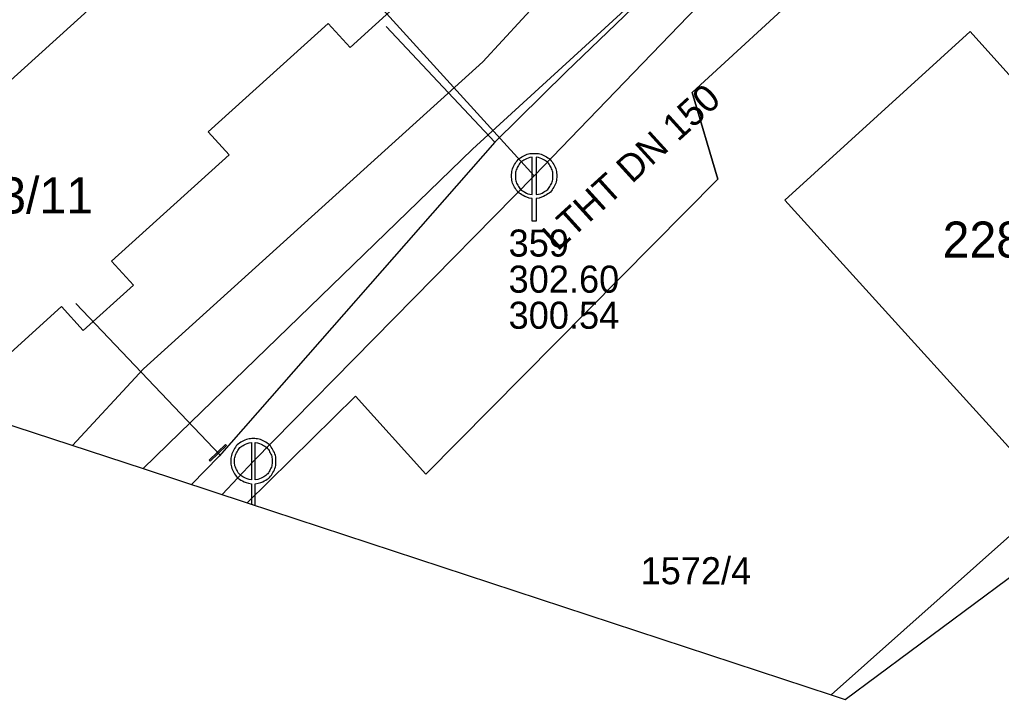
# Model space of a CAD drawing. Extents: x -570890 to -570546, y -1086481 to -1086296.
# Drawn here: x -570739.5 to -570685, y -1086481.2 to -1086443.5 of the extents above; entities that cross this region are included whole.
import ezdxf

# ---------------------------------------------------------------- set-up
doc = ezdxf.new("R2010")
doc.units = 0
for name, color, linetype in [('Adresní místo-text', 7, 'Continuous'), ('Armatura vodovodní', 7, 'Continuous'), ('Default', 7, 'Continuous'), ('Kanalizační přípojka', 7, 'Continuous'), ('Kanalizační stoka', 7, 'Continuous'), ('Kanalizační šachta', 7, 'Continuous'), ('Parcela-polygon', 7, 'Continuous'), ('Parcela-text', 7, 'Continuous'), ('Popis šachty', 7, 'Continuous'), ('Vodovodní přípojka', 7, 'Continuous'), ('Vodovodní řad', 7, 'Continuous'), ('Řad vodovodní popis', 7, 'Continuous')]:
    doc.layers.add(name, color=color, linetype=linetype)

msp = doc.modelspace()

# ---------------------------------------------------------------- linework, layer by layer
at = {"layer": 'Armatura vodovodní'}
msp.add_lwpolyline([(-570727.998, -1086467.114), (-570728.903, -1086467.976), (-570728.957, -1086467.919), (-570728.052, -1086467.058), (-570727.998, -1086467.114)], dxfattribs=at)
at = {"layer": 'Default'}
for points in [[(-570711.043, -1086453.418), (-570711.301, -1086453.4), (-570711.563, -1086453.254), (-570711.86, -1086453.09), (-570712.025, -1086452.793), (-570712.19, -1086452.495), (-570712.19, -1086452.17), (-570712.19, -1086451.843), (-570712.022, -1086451.543), (-570711.853, -1086451.242), (-570711.555, -1086451.081), (-570711.257, -1086450.92), (-570710.94, -1086450.92), (-570710.625, -1086450.92), (-570710.326, -1086451.081), (-570710.027, -1086451.242), (-570709.858, -1086451.543), (-570709.69, -1086451.843), (-570709.69, -1086452.17), (-570709.69, -1086452.495), (-570709.855, -1086452.793), (-570710.02, -1086453.09), (-570710.317, -1086453.254), (-570710.579, -1086453.4), (-570710.837, -1086453.418)], [(-570711.043, -1086451.132), (-570711.24, -1086451.149), (-570711.455, -1086451.264), (-570711.704, -1086451.399), (-570711.843, -1086451.649), (-570711.982, -1086451.899), (-570711.982, -1086452.17), (-570711.982, -1086452.441), (-570711.846, -1086452.688), (-570711.709, -1086452.934), (-570711.46, -1086453.071), (-570711.248, -1086453.191), (-570711.043, -1086453.205)], [(-570710.837, -1086453.205), (-570710.632, -1086453.191), (-570710.418, -1086453.071), (-570710.171, -1086452.934), (-570710.034, -1086452.688), (-570709.898, -1086452.441), (-570709.898, -1086452.17), (-570709.898, -1086451.899), (-570710.038, -1086451.649), (-570710.178, -1086451.399), (-570710.427, -1086451.264), (-570710.64, -1086451.149), (-570710.837, -1086451.132)]]:
    msp.add_open_spline(points, degree=3, dxfattribs=at)
at = {"layer": 'Kanalizační přípojka'}
msp.add_lwpolyline([(-570720.987, -1086441.102), (-570710.94, -1086452.17)], dxfattribs=at)
at = {"layer": 'Kanalizační stoka'}
for p, q in [((-570696.56, -1086437.24), (-570710.94, -1086452.17)), ((-570710.94, -1086452.17), (-570726.51, -1086467.98)), ((-570726.51, -1086467.98), (-570728.246, -1086469.83))]:
    msp.add_line(p, q, dxfattribs=at)
at = {"layer": 'Kanalizační šachta'}
for p, q in [((-570726.613, -1086466.942), (-570726.613, -1086469.015)), ((-570726.407, -1086469.015), (-570726.407, -1086466.942)), ((-570726.613, -1086469.228), (-570726.613, -1086470.366)), ((-570726.407, -1086470.434), (-570726.407, -1086469.228)), ((-570726.613, -1086470.366), (-570726.407, -1086470.434))]:
    msp.add_line(p, q, dxfattribs=at)
for points in [[(-570711.043, -1086453.205), (-570711.043, -1086451.132)], [(-570710.837, -1086451.132), (-570710.837, -1086453.205)], [(-570710.837, -1086453.418), (-570710.837, -1086454.67), (-570711.043, -1086454.67), (-570711.043, -1086453.418)]]:
    msp.add_lwpolyline(points, dxfattribs=at)
for points in [[(-570726.407, -1086469.228), (-570726.149, -1086469.21), (-570725.887, -1086469.064), (-570725.59, -1086468.9), (-570725.425, -1086468.603), (-570725.26, -1086468.305), (-570725.26, -1086467.98), (-570725.26, -1086467.653), (-570725.428, -1086467.353), (-570725.597, -1086467.052), (-570725.896, -1086466.891), (-570726.195, -1086466.73), (-570726.51, -1086466.73), (-570726.827, -1086466.73), (-570727.125, -1086466.891), (-570727.423, -1086467.052), (-570727.592, -1086467.353), (-570727.76, -1086467.653), (-570727.76, -1086467.98), (-570727.76, -1086468.305), (-570727.595, -1086468.603), (-570727.43, -1086468.9), (-570727.133, -1086469.064), (-570726.871, -1086469.21), (-570726.613, -1086469.228)], [(-570726.613, -1086469.015), (-570726.818, -1086469.001), (-570727.03, -1086468.881), (-570727.279, -1086468.744), (-570727.416, -1086468.498), (-570727.552, -1086468.251), (-570727.552, -1086467.98), (-570727.552, -1086467.709), (-570727.413, -1086467.459), (-570727.274, -1086467.209), (-570727.025, -1086467.074), (-570726.81, -1086466.959), (-570726.613, -1086466.942)], [(-570726.407, -1086466.942), (-570726.21, -1086466.959), (-570725.997, -1086467.074), (-570725.748, -1086467.209), (-570725.608, -1086467.459), (-570725.468, -1086467.709), (-570725.468, -1086467.98), (-570725.468, -1086468.251), (-570725.604, -1086468.498), (-570725.741, -1086468.744), (-570725.988, -1086468.881), (-570726.202, -1086469.001), (-570726.407, -1086469.015)]]:
    msp.add_open_spline(points, degree=3, dxfattribs=at)
at = {"layer": 'Parcela-polygon'}
for p, q in [((-570743.23, -1086464.907), (-570732.62, -1086468.393)), ((-570732.62, -1086468.393), (-570726.856, -1086470.287)), ((-570726.856, -1086470.287), (-570694.475, -1086480.924))]:
    msp.add_line(p, q, dxfattribs=at)
for points in [[(-570743.23, -1086464.907), (-570737.15, -1086459.41), (-570735.94, -1086460.74), (-570733.16, -1086458.23), (-570734.37, -1086456.9), (-570727.85, -1086451.01), (-570729.02, -1086449.73), (-570722.36, -1086443.72), (-570721.15, -1086445.06), (-570718.33, -1086442.51), (-570719.54, -1086441.17), (-570706.72, -1086429.59), (-570705.51, -1086430.93), (-570702.69, -1086428.39), (-570703.9, -1086427.05), (-570697.39, -1086421.17), (-570704.98, -1086412.95), (-570736.47, -1086441.32), (-570735.28, -1086442.64), (-570755.467, -1086460.887)], [(-570755.467, -1086460.887), (-570735.28, -1086442.64), (-570736.47, -1086441.32), (-570704.98, -1086412.95), (-570697.39, -1086421.17), (-570703.9, -1086427.05), (-570702.69, -1086428.39), (-570705.51, -1086430.93), (-570706.72, -1086429.59), (-570719.54, -1086441.17), (-570718.33, -1086442.51), (-570721.15, -1086445.06), (-570722.36, -1086443.72), (-570729.02, -1086449.73), (-570727.85, -1086451.01), (-570734.37, -1086456.9), (-570733.16, -1086458.23), (-570735.94, -1086460.74), (-570737.15, -1086459.41), (-570743.23, -1086464.907)], [(-570726.856, -1086470.287), (-570720.84, -1086464.38), (-570716.94, -1086468.7), (-570700.75, -1086452.36), (-570702.17, -1086447.55), (-570695.62, -1086441.51), (-570687.38, -1086434.77), (-570685.19, -1086433.4), (-570683.47, -1086432.73), (-570681.75, -1086432.33), (-570680.36, -1086432.34), (-570685.68, -1086426.55), (-570687.54, -1086424.56), (-570687.78, -1086425.47), (-570688.21, -1086426.47), (-570688.87, -1086427.37), (-570714.36, -1086450.68), (-570730.58, -1086466.4), (-570732.62, -1086468.393)], [(-570732.62, -1086468.393), (-570730.58, -1086466.4), (-570714.36, -1086450.68), (-570688.87, -1086427.37)], [(-570665.603, -1086460.368), (-570659.48, -1086455.08), (-570680.36, -1086432.34), (-570681.75, -1086432.33), (-570683.47, -1086432.73), (-570685.19, -1086433.4), (-570687.38, -1086434.77), (-570695.62, -1086441.51), (-570702.17, -1086447.55), (-570700.75, -1086452.36), (-570716.94, -1086468.7), (-570720.84, -1086464.38), (-570726.856, -1086470.287)], [(-570680.682, -1086471.538), (-570697.04, -1086453.52), (-570686.77, -1086444.17), (-570669.556, -1086463.296)], [(-570669.556, -1086463.296), (-570686.77, -1086444.17), (-570697.04, -1086453.52), (-570680.682, -1086471.538)], [(-570694.475, -1086480.924), (-570682.38, -1086470.18), (-570681.14, -1086471.877)], [(-570681.14, -1086471.877), (-570682.38, -1086470.18), (-570694.475, -1086480.924)], [(-570694.475, -1086480.924), (-570693.697, -1086481.179), (-570681.14, -1086471.877)]]:
    msp.add_lwpolyline(points, dxfattribs=at)
at = {"layer": 'Vodovodní přípojka'}
for points in [[(-570719.142, -1086443.892), (-570713.124, -1086450.31)], [(-570736.351, -1086459.244), (-570728.357, -1086467.643)]]:
    msp.add_lwpolyline(points, dxfattribs=at)
at = {"layer": 'Vodovodní řad'}
for points in [[(-570671.61, -1086415.74), (-570690.154, -1086424.461), (-570693.008, -1086425.972), (-570699.396, -1086431.613), (-570708.97, -1086440.64), (-570710.52, -1086442.29), (-570713.79, -1086445.84), (-570732.603, -1086462.857), (-570736.531, -1086467.108)], [(-570709.167, -1086446.396), (-570698.124, -1086435.809), (-570694.807, -1086432.821), (-570694.63, -1086433.04)], [(-570709.167, -1086446.396), (-570713.123, -1086450.309), (-570728.403, -1086467.695), (-570729.94, -1086469.273)]]:
    msp.add_lwpolyline(points, dxfattribs=at)

# ---------------------------------------------------------------- texts
at = {"layer": 'Adresní místo-text'}
for s, p in [('313/11', (-570743.581, -1086454.25)), ('228/12', (-570688.291, -1086456.7))]:
    msp.add_text(s, height=2, dxfattribs=at).set_placement(p)
at = {"layer": 'Parcela-text'}
msp.add_text('1572/4', height=1.5, dxfattribs=at).set_placement((-570705.04, -1086474.8))
at = {"layer": 'Popis šachty'}
for s, p in [('359', (-570712.358, -1086456.642)), ('302.60', (-570712.358, -1086458.642)), ('300.54', (-570712.358, -1086460.642))]:
    msp.add_text(s, height=1.5, dxfattribs=at).set_placement(p)
at = {"layer": 'Řad vodovodní popis'}
msp.add_text('LTHT DN 150', height=1.5, rotation=42.3036, dxfattribs=at).set_placement((-570709.647, -1086456.389))

doc.saveas('drawing.dxf')
